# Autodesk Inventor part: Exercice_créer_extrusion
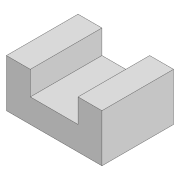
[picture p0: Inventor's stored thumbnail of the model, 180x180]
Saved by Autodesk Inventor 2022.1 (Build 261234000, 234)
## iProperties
Created: 2021-05
Part Number: Exercice_créer_extrusion
Material: Générique
Document SubType Name: Modeling
Designer: Fabian
Density: 1 g/cm^3
Appearance: Par défaut
Mass: 2.25 g
Surface Area: 13.5 cm^2
Volume: 2.25 cm^3
Author: Fabian
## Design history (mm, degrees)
sketch "Esquisse1"
  geometry: L1 (0, 0)-(0, 10); L2 (5, 10)-(10, 10); L3 (10, 10)-(10, 0); L4 (10, 0)-(-10, 0); L5 (-10, 0)-(-10, 10); L6 (-10, 10)-(-5, 10); L7 (-5, 10)-(-5, 5); L8 (-5, 5)-(5, 5); L9 (5, 5)-(5, 10)
  constraints: 18 end point, 5 perpendicular, 2 point on line, 2 vertical, 1 horizontal, 1 horizontal alignment, 1 midpoint, 1 other
  dimensions: "d4" = 10 distance of L4.end L5.end; "d5" = 5 distance of L6.end L7.end; "d6" = 20 distance of L3.end L4.end; "d7" = 10 distance of L7.end L8.end
extrude "Extrusion1" new body sketch "Esquisse1" distance "d8" = 10; taper "d10" = 0 deg; dims "d9" = 5, "d11" = 0
node "Solide1"
